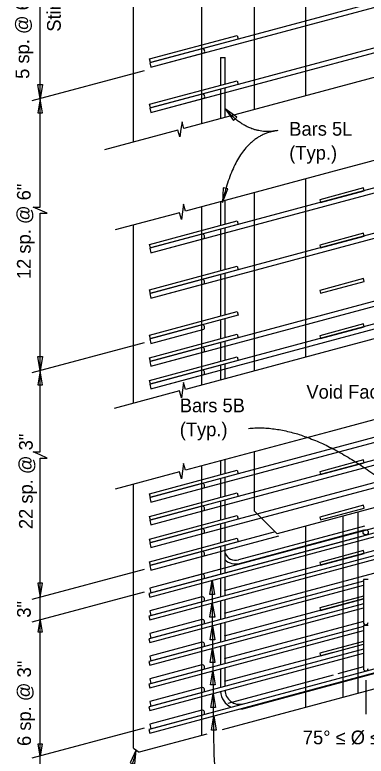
# Model space of a CAD drawing. Extents: x 120700.3 to 120754.4, y 120608.4 to 120631.3.
# Drawn here: x 120719.45 to 120723.33, y 120614.68 to 120622.85 of the extents above; entities that cross this region are included whole.
import ezdxf

# ---------------------------------------------------------------- set-up
doc = ezdxf.new("R2010")
doc.units = 0
for name, color, linetype in [('BeamConc', 7, 'Continuous'), ('BeamConc_h', 7, 'Continuous'), ('Dimension', 7, 'Continuous'), ('Miscellaneous', 7, 'Continuous'), ('Rebar', 7, 'Continuous'), ('Rebar_h', 7, 'Continuous'), ('TextStructures', 7, 'Continuous')]:
    doc.layers.add(name, color=color, linetype=linetype)

msp = doc.modelspace()

# ---------------------------------------------------------------- linework, layer by layer
at = {"layer": 'BeamConc'}
for p, q in [((120720.758, 120621.4519), (120720.758, 120627.8043)), ((120722.0913, 120621.809), (120722.0913, 120627.8043)), ((120722.0912, 120618.9268), (120722.0912, 120620.8934)), ((120720.7579, 120618.5696), (120720.7579, 120620.5362)), ((120726.4154, 120618.2211), (120722.3412, 120617.1295)), ((120722.0912, 120617.3795), (120722.0912, 120618.0345)), ((120720.7579, 120614.7677), (120720.7579, 120617.6773)), ((120722.3412, 120617.1295), (120722.0912, 120617.3795)), ((120729.1559, 120616.9555), (120721.7359, 120614.9673)), ((120721.5659, 120614.9217), (120720.8183, 120614.7214)), ((120720.7579, 120614.7677), (120720.8183, 120614.7214))]:
    msp.add_line(p, q, dxfattribs=at)
at = {"layer": 'BeamConc_h'}
for p, q in [((120722.6538, 120627.8043), (120722.6538, 120621.9598)), ((120721.5079, 120627.7225), (120721.5079, 120621.6528)), ((120722.6537, 120621.0441), (120722.6537, 120619.0775)), ((120721.5079, 120620.7372), (120721.5079, 120618.7706)), ((120721.5079, 120617.8782), (120721.5079, 120614.9062)), ((120722.6537, 120617.2132), (120722.6537, 120615.2132))]:
    msp.add_line(p, q, dxfattribs=at)
at = {"layer": 'Dimension'}
for p, q in [((120720.8725, 120622.2359), (120719.6348, 120621.9043)), ((120720.8724, 120619.2359), (120719.6348, 120618.9043)), ((120720.8724, 120616.7359), (120719.6348, 120616.4043)), ((120720.8724, 120616.4859), (120719.6348, 120616.1543)), ((120723.3204, 120615.5172), (120723.3204, 120615.1411)), ((120720.8724, 120614.9859), (120719.6348, 120614.6543))]:
    msp.add_line(p, q, dxfattribs=at)
for points in [[(120719.7265, 120621.9289), (120719.7265, 120628.0654)], [(120724.9897, 120622.5353), (120724.9772, 120622.5821), (120722.272, 120621.8575)], [(120727.0943, 120622.2335), (120725.0196, 120621.6778), (120724.9996, 120621.7526), (120724.9871, 120621.6691), (120724.9744, 120621.5854), (120724.9544, 120621.6603), (120722.9331, 120621.1189)], [(120719.7265, 120618.9289), (120719.7265, 120620.6659), (120719.804, 120620.6659), (120719.7265, 120620.6996), (120719.649, 120620.7334), (120719.7265, 120620.7334), (120719.7265, 120621.9289)], [(120722.272, 120621.8575), (120721.3128, 120621.6005), (120721.2928, 120621.6753), (120721.2803, 120621.5918), (120721.2676, 120621.5081), (120721.2476, 120621.583), (120720.4363, 120621.3657)], [(120722.9331, 120621.1189), (120721.3298, 120620.6895), (120721.3098, 120620.7643), (120721.2973, 120620.6807), (120721.2846, 120620.5971), (120721.2646, 120620.672), (120720.5531, 120620.4814)], [(120727.0943, 120620.2669), (120725.0196, 120619.7112), (120724.9996, 120619.786), (120724.9871, 120619.7024), (120724.9744, 120619.6188), (120724.9544, 120619.6937), (120722.9331, 120619.1523)], [(120727.3072, 120619.4316), (120725.0196, 120618.8189), (120724.9996, 120618.8936), (120724.9871, 120618.8101), (120724.9744, 120618.7265), (120724.9544, 120618.8014), (120722.9331, 120618.2599)], [(120722.9331, 120619.1523), (120721.3298, 120618.7229), (120721.3098, 120618.7977), (120721.2973, 120618.7141), (120721.2846, 120618.6305), (120721.2646, 120618.7054), (120720.5445, 120618.5124)], [(120719.7265, 120613.8833), (120719.7265, 120617.9657), (120719.804, 120617.9657), (120719.7265, 120617.9995), (120719.649, 120618.0332), (120719.7265, 120618.0332), (120719.7265, 120618.9289)], [(120722.9331, 120618.2599), (120721.3298, 120617.8305), (120721.3098, 120617.9053), (120721.2973, 120617.8218), (120721.2846, 120617.7381), (120721.2646, 120617.813), (120720.5535, 120617.6225)]]:
    msp.add_lwpolyline(points, dxfattribs=at)
for points in [[(120719.7265, 120621.9289), (120719.7, 120622.085), (120719.7529, 120622.085)], [(120719.7265, 120621.9289), (120719.7, 120621.7727), (120719.7529, 120621.7727)], [(120721.7683, 120621.8185), (120721.8589, 120621.6885), (120721.8966, 120621.7256)], [(120721.7399, 120620.7859), (120721.7979, 120620.9334), (120721.7461, 120620.9442)], [(120719.7265, 120618.9289), (120719.7, 120619.085), (120719.7529, 120619.085)], [(120719.7265, 120618.9289), (120719.7, 120618.7727), (120719.7529, 120618.7727)], [(120719.7265, 120616.4289), (120719.7529, 120616.585), (120719.7, 120616.585)], [(120721.6255, 120616.6176), (120721.652, 120616.4614), (120721.5991, 120616.4614)], [(120721.6265, 120616.3678), (120721.6529, 120616.2116), (120721.6, 120616.2116)], [(120719.7265, 120616.1786), (120719.7486, 120616.0448), (120719.7044, 120616.0448)], [(120721.6277, 120616.1182), (120721.6542, 120615.962), (120721.6012, 120615.962)], [(120721.6297, 120615.8686), (120721.6561, 120615.7125), (120721.6032, 120615.7125)], [(120721.6324, 120615.6194), (120721.6589, 120615.4632), (120721.6059, 120615.4632)], [(120721.6363, 120615.3704), (120721.6627, 120615.2142), (120721.6098, 120615.2142)], [(120721.6423, 120615.1221), (120721.6688, 120614.9659), (120721.6158, 120614.9659)], [(120719.7265, 120614.6786), (120719.7044, 120614.8123), (120719.7486, 120614.8123)], [(120720.7872, 120614.746), (120720.7195, 120614.6028), (120720.7705, 120614.5885)]]:
    msp.add_lwpolyline(points, close=True, dxfattribs=at)
for points in [[(120722.3496, 120621.5778), (120722.0271, 120621.5134), (120721.7683, 120621.8185)], [(120722.3496, 120621.5778), (120721.8942, 120621.5226), (120721.74, 120620.786)], [(120722.026, 120618.2931), (120722.8238, 120618.3724), (120723.9611, 120617.336)], [(120722.0377, 120614.2564), (120721.7448, 120614.2247), (120721.6513, 120614.5352), (120721.6431, 120614.8832), (120721.6256, 120616.6176)], [(120720.7867, 120614.7457), (120720.7061, 120614.4034), (120720.1901, 120613.6162), (120720.6227, 120613.6072)]]:
    msp.add_open_spline(points, degree=2, dxfattribs=at)
at = {"layer": 'Miscellaneous'}
for p, q in [((120723.0663, 120617.3237), (120723.0663, 120615.3237)), ((120723.233, 120617.3684), (120723.233, 120615.3684))]:
    msp.add_line(p, q, dxfattribs=at)
at = {"layer": 'Rebar'}
for p, q in [((120720.9346, 120622.3688), (120721.9006, 120622.6276)), ((120721.9114, 120622.5873), (120720.9454, 120622.3285)), ((120721.9006, 120622.6276), (120721.9114, 120622.5873)), ((120721.5097, 120622.4797), (120720.936, 120622.326)), ((120720.9495, 120622.2757), (120721.5232, 120622.4294)), ((120720.9454, 120622.3285), (120720.9346, 120622.3688)), ((120720.936, 120622.326), (120720.9495, 120622.2757)), ((120721.7163, 120622.3839), (120721.7163, 120622.0782)), ((120721.7163, 120622.3839), (120721.7684, 120622.3839)), ((120721.7684, 120622.0922), (120721.7684, 120622.3839)), ((120720.9346, 120621.8688), (120721.9006, 120622.1276)), ((120721.9114, 120622.0873), (120720.9454, 120621.8285)), ((120721.9006, 120622.1276), (120721.9114, 120622.0873)), ((120721.7163, 120622.035), (120721.7163, 120621.7086)), ((120721.7684, 120621.7226), (120721.7684, 120622.0489)), ((120721.5097, 120621.9797), (120720.936, 120621.826)), ((120720.9495, 120621.7757), (120721.5232, 120621.9294)), ((120720.9454, 120621.8285), (120720.9346, 120621.8688)), ((120720.936, 120621.826), (120720.9495, 120621.7757)), ((120721.7163, 120620.793), (120721.7163, 120620.5322)), ((120721.7683, 120620.5461), (120721.7683, 120620.8069)), ((120720.9346, 120620.3227), (120721.9006, 120620.5815)), ((120721.9113, 120620.5413), (120720.9454, 120620.2824)), ((120721.9006, 120620.5815), (120721.9113, 120620.5413)), ((120721.5097, 120620.4336), (120720.936, 120620.2799)), ((120721.7163, 120620.489), (120721.7163, 120620.0322)), ((120721.7683, 120620.0461), (120721.7683, 120620.5029)), ((120720.9494, 120620.2296), (120721.5232, 120620.3833)), ((120720.9454, 120620.2824), (120720.9346, 120620.3227)), ((120720.936, 120620.2799), (120720.9494, 120620.2296)), ((120720.9346, 120619.8227), (120721.9006, 120620.0815)), ((120721.9113, 120620.0413), (120720.9454, 120619.7824)), ((120721.9006, 120620.0815), (120721.9113, 120620.0413)), ((120721.7163, 120619.989), (120721.7163, 120619.5322)), ((120721.7683, 120619.5461), (120721.7683, 120620.0029)), ((120721.5097, 120619.9336), (120720.936, 120619.7799)), ((120720.9494, 120619.7296), (120721.5232, 120619.8833)), ((120720.9454, 120619.7824), (120720.9346, 120619.8227)), ((120720.936, 120619.7799), (120720.9494, 120619.7296)), ((120720.9346, 120619.3227), (120721.9006, 120619.5815)), ((120721.9113, 120619.5413), (120720.9454, 120619.2824)), ((120721.9006, 120619.5815), (120721.9113, 120619.5413)), ((120721.7163, 120619.489), (120721.7163, 120619.2822)), ((120721.7683, 120619.2961), (120721.7683, 120619.5029)), ((120721.5097, 120619.4336), (120720.936, 120619.2799)), ((120720.9494, 120619.2296), (120721.5232, 120619.3833)), ((120720.9346, 120619.0727), (120721.9006, 120619.3315)), ((120720.9454, 120619.2824), (120720.9346, 120619.3227)), ((120721.9113, 120619.2913), (120720.9454, 120619.0324)), ((120721.9006, 120619.3315), (120721.9113, 120619.2913)), ((120720.936, 120619.2799), (120720.9494, 120619.2296)), ((120721.7163, 120619.239), (120721.7163, 120619.0322)), ((120721.7683, 120619.0461), (120721.7683, 120619.2529)), ((120721.5097, 120619.1836), (120720.936, 120619.0299)), ((120720.9494, 120618.9796), (120721.5232, 120619.1333)), ((120720.9346, 120618.8227), (120721.9006, 120619.0815)), ((120720.9454, 120619.0324), (120720.9346, 120619.0727)), ((120721.9113, 120619.0413), (120720.9454, 120618.7824)), ((120721.9006, 120619.0815), (120721.9113, 120619.0413)), ((120720.936, 120619.0299), (120720.9494, 120618.9796)), ((120721.7163, 120618.989), (120721.7163, 120618.8264)), ((120721.7683, 120618.8403), (120721.7683, 120619.0029)), ((120721.5097, 120618.9336), (120720.936, 120618.7799)), ((120720.9494, 120618.7296), (120721.5232, 120618.8833)), ((120720.9454, 120618.7824), (120720.9346, 120618.8227)), ((120720.936, 120618.7799), (120720.9494, 120618.7296)), ((120729.0388, 120618.3971), (120720.9246, 120616.2229)), ((120720.9354, 120616.1826), (120729.0496, 120618.3568)), ((120727.5804, 120618.2563), (120720.9246, 120616.4729)), ((120720.9354, 120616.4326), (120727.5878, 120618.2152)), ((120721.7163, 120617.934), (120721.7163, 120617.7822)), ((120721.7683, 120617.7961), (120721.7683, 120617.948)), ((120720.9346, 120617.5727), (120721.9006, 120617.8315)), ((120721.9006, 120617.8315), (120721.9113, 120617.7913)), ((120721.9113, 120617.7913), (120720.9454, 120617.5324)), ((120721.7163, 120617.739), (120721.7163, 120617.5322)), ((120721.7683, 120617.5461), (120721.7683, 120617.7529)), ((120721.5097, 120617.6836), (120720.936, 120617.5299)), ((120720.9346, 120617.3227), (120721.9006, 120617.5815)), ((120720.9454, 120617.5324), (120720.9346, 120617.5727)), ((120720.9494, 120617.4796), (120721.5232, 120617.6333)), ((120721.9006, 120617.5815), (120721.9113, 120617.5413)), ((120720.936, 120617.5299), (120720.9494, 120617.4796)), ((120721.9113, 120617.5413), (120720.9454, 120617.2824)), ((120721.7163, 120617.4889), (120721.7163, 120617.2822)), ((120721.7683, 120617.2961), (120721.7683, 120617.5029)), ((120721.5097, 120617.4336), (120720.936, 120617.2799)), ((120720.9346, 120617.0727), (120721.9006, 120617.3315)), ((120720.9454, 120617.2824), (120720.9346, 120617.3227)), ((120720.9494, 120617.2296), (120721.5232, 120617.3833)), ((120721.9006, 120617.3315), (120721.9113, 120617.2913)), ((120720.936, 120617.2799), (120720.9494, 120617.2296)), ((120721.9113, 120617.2913), (120720.9454, 120617.0324)), ((120721.7163, 120617.2389), (120721.7163, 120617.0322)), ((120721.7683, 120617.0461), (120721.7683, 120617.2529)), ((120721.5097, 120617.1836), (120720.936, 120617.0299)), ((120723.3071, 120617.2157), (120721.9153, 120616.8428)), ((120721.9261, 120616.804), (120723.305, 120617.1735)), ((120720.9346, 120616.8227), (120721.9006, 120617.0815)), ((120720.9494, 120616.9796), (120721.5232, 120617.1333)), ((120721.9006, 120617.0815), (120721.9113, 120617.0413)), ((120720.9454, 120617.0324), (120720.9346, 120617.0727)), ((120720.936, 120617.0299), (120720.9494, 120616.9796)), ((120721.9113, 120617.0413), (120720.9454, 120616.7824)), ((120721.7683, 120616.699), (120721.7683, 120617.0029)), ((120721.5097, 120616.9336), (120720.936, 120616.7799)), ((120721.7163, 120616.9889), (120721.7163, 120616.685)), ((120727.8702, 120616.834), (120720.9246, 120614.9729)), ((120720.9494, 120616.7296), (120721.5232, 120616.8833)), ((120721.9785, 120615.2049), (120728.1035, 120616.8461)), ((120720.9454, 120616.7824), (120720.9346, 120616.8227)), ((120720.9354, 120614.9326), (120727.8827, 120616.7942)), ((120720.936, 120616.7799), (120720.9494, 120616.7296)), ((120721.5097, 120616.6836), (120720.936, 120616.5299)), ((120723.2944, 120616.6079), (120720.9246, 120615.9729)), ((120720.9494, 120616.4796), (120721.5232, 120616.6333)), ((120721.7163, 120616.6419), (120721.7163, 120616.435)), ((120721.7683, 120616.449), (120721.7683, 120616.6558)), ((120723.2944, 120616.6279), (120723.2944, 120616.1539)), ((120723.3464, 120616.6279), (120723.2944, 120616.6279)), ((120720.9354, 120615.9326), (120723.2944, 120616.5647)), ((120720.936, 120616.5299), (120720.9494, 120616.4796)), ((120720.9246, 120616.4729), (120720.9354, 120616.4326)), ((120721.5097, 120616.4336), (120720.936, 120616.2799)), ((120723.2944, 120616.3579), (120720.9246, 120615.7229)), ((120720.9494, 120616.2296), (120721.5232, 120616.3833)), ((120721.7163, 120616.3919), (120721.7163, 120616.185)), ((120721.7683, 120616.199), (120721.7683, 120616.4058)), ((120720.9354, 120615.6826), (120723.2944, 120616.3147)), ((120720.936, 120616.2799), (120720.9494, 120616.2296)), ((120720.9246, 120616.2229), (120720.9354, 120616.1826)), ((120721.5097, 120616.1836), (120720.936, 120616.0299)), ((120723.2944, 120616.1079), (120720.9246, 120615.4729)), ((120720.9494, 120615.9796), (120721.5232, 120616.1333)), ((120721.7163, 120616.1419), (120721.7163, 120615.935)), ((120721.7683, 120615.949), (120721.7683, 120616.1558)), ((120723.2944, 120616.1179), (120723.2944, 120615.6439)), ((120723.3464, 120616.1179), (120723.2944, 120616.1179)), ((120720.9354, 120615.4326), (120723.2944, 120616.0647)), ((120720.936, 120616.0299), (120720.9494, 120615.9796)), ((120720.9246, 120615.9729), (120720.9354, 120615.9326)), ((120721.5097, 120615.9336), (120720.936, 120615.7799)), ((120723.2944, 120615.8579), (120720.9246, 120615.2229)), ((120720.9494, 120615.7296), (120721.5232, 120615.8833)), ((120721.7163, 120615.8919), (120721.7163, 120615.6851)), ((120721.7683, 120615.699), (120721.7683, 120615.9058)), ((120720.9354, 120615.1826), (120723.2944, 120615.8147)), ((120720.936, 120615.7799), (120720.9494, 120615.7296)), ((120720.9246, 120615.7229), (120720.9354, 120615.6826)), ((120721.5097, 120615.6836), (120720.936, 120615.5299)), ((120720.9494, 120615.4796), (120721.5232, 120615.6333)), ((120721.7163, 120615.6419), (120721.7163, 120615.435)), ((120721.7683, 120615.449), (120721.7683, 120615.6558)), ((120720.936, 120615.5299), (120720.9494, 120615.4796)), ((120720.9246, 120615.4729), (120720.9354, 120615.4326)), ((120721.5097, 120615.4336), (120720.936, 120615.2799)), ((120720.9494, 120615.2296), (120721.5232, 120615.3833)), ((120720.936, 120615.2799), (120720.9494, 120615.2296)), ((120720.9246, 120615.2229), (120720.9354, 120615.1826)), ((120721.5097, 120615.1836), (120720.936, 120615.0299)), ((120720.9494, 120614.9796), (120721.5232, 120615.1333)), ((120720.9246, 120614.9729), (120720.9354, 120614.9326)), ((120720.936, 120615.0299), (120720.9494, 120614.9796))]:
    msp.add_line(p, q, dxfattribs=at)
for points in [[(120722.8204, 120620.7848), (120723.3034, 120620.9142), (120723.2953, 120620.9444), (120722.8123, 120620.815)], [(120722.8204, 120620.2848), (120723.3034, 120620.4142), (120723.2953, 120620.4444), (120722.8123, 120620.315)], [(120722.8204, 120619.7848), (120723.3034, 120619.9142), (120723.2953, 120619.9444), (120722.8123, 120619.815)], [(120722.8204, 120619.2848), (120723.3034, 120619.4142), (120723.2953, 120619.4444), (120722.8123, 120619.315)], [(120722.8204, 120617.7848), (120723.3034, 120617.9142), (120723.2953, 120617.9444), (120722.8123, 120617.815)], [(120722.8204, 120617.2848), (120723.3034, 120617.4142), (120723.2953, 120617.4444), (120722.8123, 120617.315)], [(120722.8204, 120616.7848), (120723.3034, 120616.9142), (120723.2953, 120616.9444), (120722.8123, 120616.815)]]:
    msp.add_lwpolyline(points, close=True, dxfattribs=at)
for points in [[(120723.2944, 120616.4441), (120722.8123, 120616.315), (120722.8204, 120616.2848), (120723.2944, 120616.4118)], [(120723.2944, 120615.9441), (120722.8123, 120615.815), (120722.8204, 120615.7848), (120723.2944, 120615.9118)]]:
    msp.add_lwpolyline(points, dxfattribs=at)
msp.add_circle((120723.3204, 120617.1468), 0.0287, dxfattribs=at)
for centre, radius, start, end in [((120721.5165, 120622.4545), 0.026, 285, 105), ((120721.5165, 120621.9545), 0.026, 285, 105), ((120721.5164, 120620.4084), 0.026, 285, 105), ((120721.5164, 120619.9084), 0.026, 285, 105), ((120721.5164, 120619.4084), 0.026, 285, 105), ((120721.5164, 120619.1584), 0.026, 285, 105), ((120721.5164, 120618.9084), 0.026, 285, 105), ((120721.5164, 120617.6584), 0.026, 285, 105), ((120721.5164, 120617.4084), 0.026, 285, 105), ((120721.5164, 120617.1584), 0.026, 285, 105), ((120721.5164, 120616.9084), 0.026, 285, 105), ((120721.8829, 120616.9635), 0.125, 203.55647, 285), ((120721.883, 120616.965), 0.1667, 226.56254, 285), ((120721.5164, 120616.6584), 0.026, 285, 105), ((120721.5164, 120616.4084), 0.026, 285, 105), ((120721.5164, 120616.1584), 0.026, 285, 105), ((120723.3204, 120616.1539), 0.026, 179.99982, 359.99949), ((120721.5164, 120615.9084), 0.026, 285, 105), ((120721.5164, 120615.6584), 0.026, 285, 105), ((120723.3204, 120615.6439), 0.026, 179.99982, 359.99949), ((120721.5164, 120615.4084), 0.026, 285, 105), ((120721.9246, 120615.4061), 0.2083, 183.86653, 245.0097), ((120721.9246, 120615.4061), 0.1562, 180, 285), ((120721.9246, 120615.4061), 0.2083, 270.06109, 285), ((120721.5164, 120615.1584), 0.026, 285, 105)]:
    msp.add_arc(centre, radius, start, end, dxfattribs=at)
at = {"layer": 'Rebar_h'}
for p, q in [((120727.3373, 120619.2451), (120721.9114, 120617.7912)), ((120721.5232, 120617.6333), (120727.3508, 120619.1949)), ((120721.5232, 120617.3833), (120727.4133, 120618.9616)), ((120727.3998, 120619.0119), (120721.9114, 120617.5412)), ((120721.5232, 120617.1333), (120727.4758, 120618.7284)), ((120727.4623, 120618.7786), (120721.9114, 120617.2912)), ((120727.5735, 120618.3084), (120720.936, 120616.5299)), ((120720.936, 120617.2799), (120720.9494, 120617.2296)), ((120722.32, 120617.1507), (120720.936, 120616.7799)), ((120720.9494, 120616.7296), (120722.3625, 120617.1082)), ((120720.9494, 120616.4796), (120723.2944, 120617.1079)), ((120720.936, 120617.0299), (120720.9494, 120616.9796)), ((120720.936, 120616.7799), (120720.9494, 120616.7296)), ((120720.936, 120616.5299), (120720.9494, 120616.4796)), ((120723.2944, 120615.6618), (120723.0131, 120615.5864)), ((120722.961, 120615.5725), (120721.7962, 120615.2603)), ((120720.936, 120615.0299), (120720.9494, 120614.9796))]:
    msp.add_line(p, q, dxfattribs=at)
for points in [[(120729.0253, 120624.4934), (120720.936, 120622.3259), (120720.9495, 120622.2757), (120729.0388, 120624.4432)], [(120729.0253, 120623.9934), (120720.936, 120621.8259), (120720.9495, 120621.7757), (120729.0388, 120623.9431)], [(120729.0149, 120622.4446), (120720.936, 120620.2799), (120720.9494, 120620.2296), (120729.0283, 120622.3944)], [(120729.0149, 120621.9446), (120720.936, 120619.7799), (120720.9494, 120619.7296), (120729.0283, 120621.8944)], [(120729.0149, 120621.1946), (120720.936, 120619.0299), (120720.9494, 120618.9796), (120729.0283, 120621.1444)], [(120729.0149, 120620.9446), (120720.936, 120618.7799), (120720.9494, 120618.7296), (120729.0283, 120620.8944)]]:
    msp.add_lwpolyline(points, close=True, dxfattribs=at)
for points in [[(120728.2163, 120618.2306), (120721.7579, 120616.5001)], [(120728.2163, 120617.9806), (120721.7579, 120616.2501)], [(120723.2944, 120616.4118), (120721.7579, 120616.0001)], [(120723.2944, 120616.1618), (120721.7579, 120615.7501)], [(120722.961, 120615.8225), (120721.7579, 120615.5001)]]:
    msp.add_lwpolyline(points, dxfattribs=at)

# ---------------------------------------------------------------- texts
at = {"layer": 'Dimension'}
for s, p in [('Bars 5L', (120722.4764, 120621.5209)), ('(Typ.)', (120722.4764, 120621.2569)), ('Bars 5B', (120721.2671, 120618.4703)), ('(Typ.)', (120721.2671, 120618.2063))]:
    msp.add_text(s, height=0.1512, dxfattribs=at).set_placement(p)
at = {"layer": 'TextStructures'}
for s, p in [('5 sp. @ 6" (along ℄ of Beam)', (120719.6052, 120622.1477)), ('Stirrup Transition Zone ', (120719.9535, 120622.6676)), ('12 sp. @ 6" ', (120719.621, 120619.9394)), ('22 sp. @ 3"', (120719.6435, 120617.1821)), ('3"', (120719.6221, 120616.2048)), ('6 sp. @ 3"', (120719.6244, 120614.7901))]:
    msp.add_text(s, height=0.1512, rotation=90, dxfattribs=at).set_placement(p)
for s, p in [('Void Face', (120722.6655, 120618.6208)), ('75° ≤ Ø ≤ 90°', (120722.6262, 120614.809))]:
    msp.add_text(s, height=0.1512, dxfattribs=at).set_placement(p)

doc.saveas('drawing.dxf')
